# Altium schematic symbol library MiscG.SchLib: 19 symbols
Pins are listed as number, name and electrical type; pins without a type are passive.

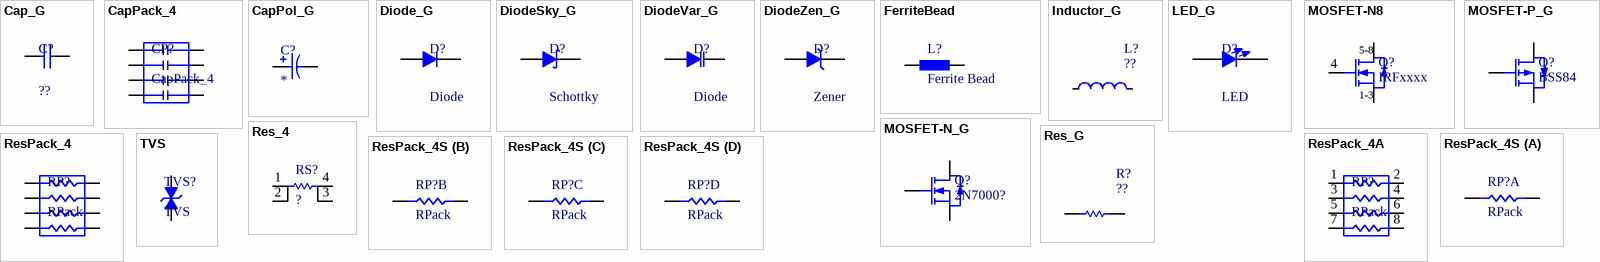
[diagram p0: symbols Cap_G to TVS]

## Cap_G
designator C?, comment ??
Capacitor
footprint RESC1608N (Chip Resistor, Body 1.6x0.8mm, IPC Medium Density)
simulation model CAP (Capacitor)
signal-integrity model Cap
pins: 1, 2

## CapPack_4
designator CP?
pins: 1, 2, 3, 4, 5, 6, 7, 8

## CapPol_G
designator C?
Polarized Capacitor
pins: 1, 2

## Diode_G
designator D?, comment Diode
Default Diode
footprint SMC (DO-214-AB/SMC; 2 C-Bend Leads; Body 7.9 x 5.9 mm, inc. leads (LxW))
simulation model DIODE (Diode)
signal-integrity model Diode
pins: 1 A, 2 K

## DiodeSky_G
designator D?, comment Schottky
Schottky Diode
footprint SMC (DO-214-AB/SMC; 2 C-Bend Leads; Body 7.9 x 5.9 mm, inc. leads (LxW))
simulation model SKYDIODE (Diode)
signal-integrity model Diode
pins: 1 A, 2 K

## DiodeVar_G
designator D?, comment Diode
Default Diode
footprint SMC (DO-214-AB/SMC; 2 C-Bend Leads; Body 7.9 x 5.9 mm, inc. leads (LxW))
pins: 1 A, 2 K

## DiodeZen_G
designator D?, comment Zener
Default Diode
footprint SMC (DO-214-AB/SMC; 2 C-Bend Leads; Body 7.9 x 5.9 mm, inc. leads (LxW))
simulation model ZENER (Diode)
signal-integrity model Diode
pins: 1 A, 2 K

## FerriteBead
designator L?, comment Ferrite Bead
pins: 1, 2

## Inductor_G
designator L?, comment ??
Inductor
pins: 1, 2

## LED_G
designator D?, comment LED
simulation model LED2 (Diode)
signal-integrity model Diode
footprint DIO1608N (Chip LED, Body 1.6x0.8mm, IPC Medium Density)
pins: 1 A, 2 K

## MOSFET-N8
designator Q?, comment IRFxxxx
N-Channel MOSFET
footprint SO8 (Small Outline; 8 Leads; Body Width 3.9 mm; Pitch 1.27 mm)
simulation model NMOS (MOSFET-N)
pins: 1 S, 2 S, 3 S, 4 G, 5 D, 6 D, 7 D, 8 D

## MOSFET-N_G
designator Q?, comment 2N7000?
N-Channel MOSFET
footprint SOT23-3N (SOT23, 3-Leads, Body 2.9x1.3mm, Pitch 0.95mm, Lead Span 2.5mm, IPC Medium Density); pin to pad D>3 G>1 S>2
simulation model NMOS (MOSFET-N)
pins: D, G, S

## MOSFET-P_G
designator Q?, comment BSS84
P-Channel MOSFET
footprint SOT23-3N (SOT23, 3-Leads, Body 2.9x1.3mm, Pitch 0.95mm, Lead Span 2.5mm, IPC Medium Density); pin to pad D>3 G>1 S>2
simulation model PMOS (MOSFET-P)
pins: D, G, S

## Res_4
designator RS?, comment ?
pins: 1, 2, 3, 4

## Res_G
designator R?, comment ??
Resistor
footprint RESC1608N (Chip Resistor, Body 1.6x0.8mm, IPC Medium Density)
simulation model RESISTOR (Resistor)
signal-integrity model Res
footprint RESC2012N (Chip Resistor, Body 2.0x1.3mm, IPC Medium Density)
pins: 1, 2

## ResPack_4
designator RP?, comment RPack
footprint CRA06S
pins: 1, 2, 3, 4, 5, 6, 7, 8

## ResPack_4A
designator RP?, comment RPack
footprint SIP8 (Single in-line package)
pins: 1, 2, 3, 4, 5, 6, 7, 8

## ResPack_4S
designator RP?, comment RPack
footprint CRA06S
part A pins: 1, 8
part B pins: 2, 7
part C pins: 3, 6
part D pins: 4, 5

## TVS
designator TVS?
footprint DO-214AC (Surface mount diode, "SMA")
footprint SMB (DO-214-AA/SMB; 2 C-Bend Leads; Body 5.3 x 3.6 mm, inc. leads (LxW))
footprint SMC (DO-214-AB/SMC; 2 C-Bend Leads; Body 7.9 x 5.9 mm, inc. leads (LxW))
pins: 1, 2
